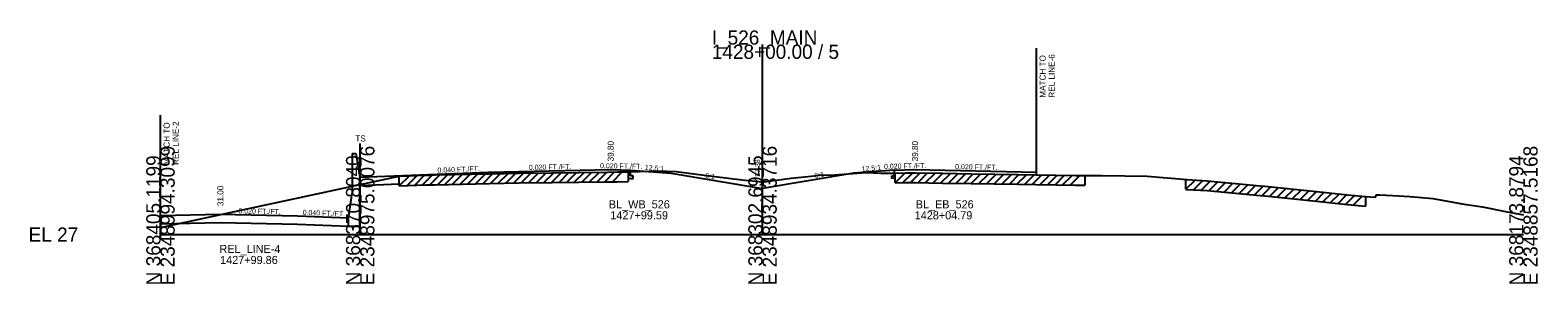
# Model space of a CAD drawing. Extents: x -170 to 2527928, y -10 to 1619750.
# Drawn here: x 3974.3 to 4271.5, y 5990.3 to 6040.3 of the extents above; entities that cross this region are included whole.
import ezdxf

# ---------------------------------------------------------------- set-up
doc = ezdxf.new("R2010")
doc.units = 0
for name, color, linetype in [('RD_GPK_XS_Cell', 7, 'Continuous'), ('RD_PD_NOISE-WALL-GM', 7, 'Continuous'), ('RD_XS_Base', 7, 'Continuous'), ('RD_XS_EarthShd', 7, 'Continuous'), ('RD_XS_ExGround', 7, 'Continuous'), ('RD_XS_ExPaveRet', 7, 'Continuous'), ('RD_XS_MatchLine', 7, 'Continuous'), ('RD_XS_Pave', 7, 'Continuous'), ('RD_XS_PaveShd', 7, 'Continuous'), ('RD_XS_TieSlope', 7, 'Continuous'), ('RD_XS_TX_Elev_EX', 7, 'Continuous'), ('RD_XS_TX_Slope', 7, 'Continuous'), ('RD_XS_TX_Station', 7, 'Continuous')]:
    doc.layers.add(name, color=color, linetype=linetype)

msp = doc.modelspace()

# ---------------------------------------------------------------- linework, layer by layer
at = {"layer": 'RD_GPK_XS_Cell'}
for p, q in [((4118.68, 6000), (4118.68, 6037.41)), ((4000, 6000), (4039.37, 6000)), ((4039.37, 6000), (4118.68, 6000)), ((4118.68, 6000), (4268.68, 6000))]:
    msp.add_line(p, q, dxfattribs=at)
at = {"layer": 'RD_PD_NOISE-WALL-GM'}
for p, q in [((4037.81, 6015.96), (4038.54, 6015.96)), ((4037.81, 6015.96), (4037.81, 6008.11)), ((4038.54, 6015.96), (4039.29, 6011.3)), ((4039.29, 6001.66), (4039.29, 6011.3)), ((4037.04, 6003.29), (4037.81, 6008.11)), ((4037.04, 6001.66), (4039.29, 6001.66))]:
    msp.add_line(p, q, dxfattribs=at)
at = {"layer": 'RD_XS_Base'}
for p, q in [((4092.68, 6011.58), (4092.68, 6012.72)), ((4144.68, 6011.59), (4144.68, 6012.72)), ((4039.29, 6009.67), (4047.08, 6009.98)), ((4047.08, 6011.5), (4047.08, 6011.62)), ((4092.21, 6011.09), (4092.68, 6011.08)), ((4093.18, 6011.57), (4092.68, 6011.58)), ((4092.68, 6011.08), (4093.18, 6011.07)), ((4093.18, 6011.07), (4093.18, 6011.57)), ((4144.18, 6011.58), (4144.68, 6011.59)), ((4144.18, 6011.08), (4144.18, 6011.58)), ((4144.68, 6011.09), (4144.18, 6011.08)), ((4144.68, 6011.09), (4144.84, 6011.09)), ((4172.68, 6011.76), (4172.68, 6012.32)), ((4000, 6002.13), (4011.75, 6002.36)), ((4011.75, 6002.36), (4027.04, 6002.06)), ((4027.04, 6002.06), (4037.04, 6001.66)), ((4037.04, 6001.66), (4037.04, 6003.29))]:
    msp.add_line(p, q, dxfattribs=at)
at = {"layer": 'RD_XS_EarthShd'}
for p, q in [((4092.68, 6012.72), (4100.68, 6012.08)), ((4144.68, 6012.72), (4136.68, 6012.08))]:
    msp.add_line(p, q, dxfattribs=at)
at = {"layer": 'RD_XS_ExGround'}
msp.add_lwpolyline([(4000, 6001.37), (4039.37, 6009.84), (4047.08, 6011.5), (4052.28, 6011.69), (4053.24, 6011.72), (4054.12, 6011.74), (4064.83, 6011.99), (4070.71, 6012.08), (4077.13, 6012.18), (4082.48, 6012.25), (4088.14, 6012.32), (4090.07, 6012.33), (4092.21, 6012.35), (4096.64, 6012.46), (4097.72, 6012.47), (4099.91, 6012.46), (4101.69, 6012.44), (4107.67, 6011.65), (4113.03, 6010.99), (4115.24, 6010.71), (4117.95, 6010.46), (4118.65, 6010.38), (4118.99, 6010.42), (4124.3, 6011.13), (4128.24, 6011.51), (4128.88, 6011.59), (4129.64, 6011.7), (4132.93, 6011.75), (4139.12, 6012.22), (4141.98, 6012.12), (4144.84, 6012.13), (4146.86, 6012.16), (4148.79, 6012.19), (4154.17, 6012.08), (4159.8, 6011.98), (4168.99, 6011.82), (4172.57, 6011.76), (4180.37, 6011.66), (4182.21, 6011.63), (4183.7, 6011.65), (4185.63, 6011.63), (4194.51, 6011.5), (4201.59, 6010.89), (4202.16, 6010.84), (4202.31, 6010.83), (4206.34, 6010.57), (4216.81, 6009.63), (4217.68, 6009.56), (4218.34, 6009.5), (4227.2, 6008.57), (4227.9, 6008.5), (4234.03, 6007.86), (4237.56, 6007.51), (4238.45, 6007.44), (4239.51, 6007.36), (4239.58, 6007.53), (4239.72, 6007.86), (4239.92, 6007.85), (4240.37, 6007.84), (4242.84, 6007.69), (4246.32, 6007.47), (4250.8, 6007.1), (4256.98, 6005.97), (4260.64, 6005.5), (4265.15, 6004.54), (4268.67, 6003.92), (4268.68, 6003.92)], dxfattribs=at)
at = {"layer": 'RD_XS_ExPaveRet'}
for p, q in [((4047.08, 6009.58), (4049.07, 6011.57)), ((4047.08, 6009.58), (4047.08, 6011.5)), ((4047.08, 6009.58), (4052.28, 6009.77)), ((4048.58, 6009.63), (4050.57, 6011.62)), ((4050.08, 6009.69), (4052.07, 6011.68)), ((4051.58, 6009.74), (4053.57, 6011.73)), ((4052.28, 6009.77), (4053.24, 6009.8)), ((4053.08, 6009.8), (4055.05, 6011.76)), ((4053.24, 6009.8), (4054.12, 6009.82)), ((4054.12, 6009.82), (4064.83, 6010.08)), ((4054.58, 6009.83), (4056.55, 6011.8)), ((4056.08, 6009.87), (4058.05, 6011.83)), ((4057.58, 6009.91), (4059.55, 6011.87)), ((4059.08, 6009.94), (4061.05, 6011.9)), ((4060.58, 6009.98), (4062.55, 6011.94)), ((4062.08, 6010.01), (4064.05, 6011.98)), ((4063.58, 6010.05), (4065.54, 6012.01)), ((4064.83, 6010.08), (4070.71, 6010.17)), ((4065.08, 6010.08), (4067.03, 6012.03)), ((4066.58, 6010.1), (4068.53, 6012.05)), ((4068.08, 6010.13), (4070.03, 6012.07)), ((4069.58, 6010.15), (4071.53, 6012.1)), ((4070.71, 6010.17), (4077.13, 6010.26)), ((4071.08, 6010.17), (4073.03, 6012.12)), ((4072.58, 6010.2), (4074.53, 6012.14)), ((4074.08, 6010.22), (4076.03, 6012.16)), ((4075.58, 6010.24), (4077.53, 6012.19)), ((4077.08, 6010.26), (4079.02, 6012.2)), ((4077.13, 6010.26), (4082.48, 6010.33)), ((4078.58, 6010.28), (4080.52, 6012.22)), ((4080.08, 6010.3), (4082.02, 6012.24)), ((4081.58, 6010.32), (4083.52, 6012.26)), ((4082.48, 6010.33), (4088.14, 6010.4)), ((4083.08, 6010.34), (4085.02, 6012.28)), ((4084.58, 6010.36), (4086.52, 6012.3)), ((4086.08, 6010.38), (4088.02, 6012.32)), ((4087.58, 6010.39), (4089.52, 6012.33)), ((4088.14, 6010.4), (4090.07, 6010.42)), ((4089.08, 6010.41), (4091.01, 6012.34)), ((4090.07, 6010.42), (4092.21, 6010.43)), ((4092.21, 6012.35), (4092.21, 6010.43)), ((4144.84, 6010.21), (4146.8, 6012.16)), ((4144.84, 6010.21), (4144.84, 6012.13)), ((4144.84, 6010.21), (4146.86, 6010.25)), ((4146.34, 6010.24), (4148.29, 6012.18)), ((4146.86, 6010.25), (4148.79, 6010.27)), ((4147.84, 6010.26), (4149.75, 6012.17)), ((4148.79, 6010.27), (4154.17, 6010.16)), ((4149.34, 6010.26), (4151.22, 6012.14)), ((4150.84, 6010.23), (4152.72, 6012.11)), ((4152.34, 6010.2), (4154.22, 6012.08)), ((4153.84, 6010.17), (4155.73, 6012.05)), ((4154.17, 6010.16), (4159.8, 6010.07)), ((4155.34, 6010.14), (4157.23, 6012.03)), ((4156.84, 6010.12), (4158.73, 6012)), ((4158.34, 6010.09), (4160.23, 6011.98)), ((4159.8, 6010.07), (4168.99, 6009.91)), ((4159.84, 6010.07), (4161.73, 6011.95)), ((4161.34, 6010.04), (4163.23, 6011.92)), ((4162.84, 6010.01), (4164.73, 6011.9)), ((4164.34, 6009.99), (4166.23, 6011.87)), ((4165.84, 6009.96), (4167.73, 6011.85)), ((4167.34, 6009.94), (4169.23, 6011.82)), ((4168.84, 6009.91), (4170.73, 6011.79)), ((4168.99, 6009.91), (4172.57, 6009.84)), ((4170.34, 6009.88), (4172.23, 6011.77)), ((4171.84, 6009.86), (4173.73, 6011.75)), ((4172.57, 6009.84), (4180.37, 6009.74)), ((4173.34, 6009.83), (4175.24, 6011.73)), ((4174.84, 6009.81), (4176.74, 6011.71)), ((4176.34, 6009.79), (4178.24, 6011.68)), ((4177.84, 6009.77), (4179.74, 6011.66)), ((4179.34, 6009.75), (4181.23, 6011.64)), ((4180.37, 6009.74), (4182.21, 6009.71)), ((4182.21, 6011.63), (4182.21, 6009.71)), ((4202.16, 6008.92), (4202.16, 6010.84)), ((4202.16, 6008.92), (4203.96, 6010.72)), ((4203.66, 6008.83), (4205.47, 6010.63)), ((4205.16, 6008.73), (4206.95, 6010.52)), ((4206.66, 6008.63), (4208.42, 6010.39)), ((4208.16, 6008.49), (4209.92, 6010.25)), ((4209.66, 6008.36), (4211.42, 6010.12)), ((4211.16, 6008.22), (4212.92, 6009.98)), ((4212.66, 6008.09), (4214.42, 6009.85)), ((4214.16, 6007.95), (4215.92, 6009.71)), ((4202.16, 6008.92), (4202.31, 6008.91)), ((4202.31, 6008.91), (4206.34, 6008.66)), ((4206.34, 6008.66), (4216.81, 6007.71)), ((4215.66, 6007.82), (4217.42, 6009.58)), ((4216.81, 6007.71), (4217.68, 6007.64)), ((4217.16, 6007.68), (4218.92, 6009.44)), ((4217.68, 6007.64), (4218.34, 6007.58)), ((4218.34, 6007.58), (4227.2, 6006.65)), ((4218.66, 6007.55), (4220.4, 6009.28)), ((4220.16, 6007.39), (4221.9, 6009.13)), ((4221.66, 6007.23), (4223.4, 6008.97)), ((4223.16, 6007.08), (4224.9, 6008.81)), ((4224.66, 6006.92), (4226.4, 6008.65)), ((4226.16, 6006.76), (4227.9, 6008.5)), ((4227.66, 6006.61), (4229.4, 6008.34)), ((4229.16, 6006.45), (4230.9, 6008.19)), ((4230.66, 6006.3), (4232.4, 6008.03)), ((4232.16, 6006.14), (4233.9, 6007.88)), ((4233.66, 6005.99), (4235.4, 6007.73)), ((4235.16, 6005.83), (4236.9, 6007.57)), ((4237.56, 6007.51), (4237.56, 6005.59)), ((4227.2, 6006.65), (4227.9, 6006.58)), ((4227.9, 6006.58), (4234.03, 6005.95)), ((4234.03, 6005.95), (4237.56, 6005.59))]:
    msp.add_line(p, q, dxfattribs=at)
at = {"layer": 'RD_XS_MatchLine'}
for p, q in [((4172.68, 6012.32), (4172.68, 6036.74)), ((4000, 5999.09), (4000, 6023.5)), ((4039.37, 6000), (4039.37, 6017.93))]:
    msp.add_line(p, q, dxfattribs=at)
at = {"layer": 'RD_XS_Pave'}
for p, q in [((4064.68, 6012.32), (4088.68, 6012.8)), ((4148.68, 6012.8), (4172.68, 6012.32)), ((4011.75, 6004), (4027.04, 6003.69))]:
    msp.add_line(p, q, dxfattribs=at)
at = {"layer": 'RD_XS_PaveShd'}
for p, q in [((4088.68, 6012.8), (4092.68, 6012.72)), ((4144.68, 6012.72), (4148.68, 6012.8)), ((4039.29, 6011.3), (4064.68, 6012.32)), ((4000, 6003.76), (4011.75, 6004)), ((4000, 6003.76), (4000, 6001.37)), ((4027.04, 6003.69), (4037.04, 6003.29))]:
    msp.add_line(p, q, dxfattribs=at)
at = {"layer": 'RD_XS_TieSlope'}
for p in [(4100.68, 6012.08), (4136.68, 6012.08)]:
    msp.add_line(p, (4118.68, 6009.08), dxfattribs=at)

# ---------------------------------------------------------------- texts
at = {"layer": 'RD_GPK_XS_Cell'}
for s, p in [('I_526_MAIN', (4108.68, 6037.41)), ('1428+00.00 / 5', (4108.68, 6034.61)), ('EL 27', (3974, 5998.6))]:
    msp.add_text(s, height=2.8, dxfattribs=at).set_placement(p)
for s, p in [('E 2348994.3099', (4002.8, 5990)), ('E 2348975.0076', (4042.17, 5990)), ('E 2348934.3716', (4121.48, 5990)), ('E 2348857.5168', (4271.48, 5990)), ('N 368405.1199', (4000, 5990)), ('N 368370.8040', (4039.37, 5990)), ('N 368302.6945', (4118.68, 5990)), ('N 368173.8794', (4268.68, 5990))]:
    msp.add_text(s, height=2.8, rotation=90, dxfattribs=at).set_placement(p)
at = {"layer": 'RD_XS_MatchLine'}
msp.add_text('TS', height=1.2, dxfattribs=at).set_placement((4038.42, 6018.34))
at = {"layer": 'RD_XS_TX_Elev_EX'}
msp.add_text('37.38', height=1, rotation=90, dxfattribs=at).set_placement((4118.18, 6011.38))
at = {"layer": 'RD_XS_TX_Slope'}
for s, rotation, p in [('0.040 FT./FT.', 2.2906, (4054.62, 6012.17)), ('0.020 FT./FT.', 1.1458, (4072.63, 6012.73)), ('0.020 FT./FT.', 358.8542, (4086.64, 6013.09)), ('12.5:1', 355.4261, (4095.44, 6012.76)), ('12.5:1', 4.5739, (4138.26, 6012.42)), ('0.020 FT./FT.', 1.1458, (4142.63, 6012.93)), ('0.020 FT./FT.', 358.8542, (4156.64, 6012.9)), ('6:1', 350.5377, (4107.32, 6011.19)), ('6:1', 9.4623, (4129.01, 6011.09)), ('0.020 FT./FT.', 358.8542, (4015.35, 6004.18)), ('0.040 FT./FT.', 357.7094, (4028, 6003.9))]:
    msp.add_text(s, height=1, rotation=rotation, dxfattribs=at).set_placement(p)
at = {"layer": 'RD_XS_TX_Station'}
for s, p in [('MATCH TO', (4174.49, 6026.97)), ('REL LINE-6 ', (4176.29, 6026.97)), ('MATCH TO', (4001.8, 6013.73)), ('REL LINE-2', (4003.6, 6013.73)), (' 39.80', (4089.34, 6013.97)), (' 39.80', (4149.34, 6013.98)), (' 31.00', (4012.41, 6005.17))]:
    msp.add_text(s, height=1.2, rotation=90, dxfattribs=at).set_placement(p)
for s, p in [('BL_WB_526', (4088.39, 6005.16)), ('BL_EB_526', (4148.88, 6005.16)), ('1427+99.59', (4088.68, 6003)), ('1428+04.79', (4148.68, 6003)), ('REL_LINE-4', (4011.63, 5996.37)), ('1427+99.86', (4011.75, 5994.2))]:
    msp.add_text(s, height=1.6, dxfattribs=at).set_placement(p)

doc.saveas('drawing.dxf')
